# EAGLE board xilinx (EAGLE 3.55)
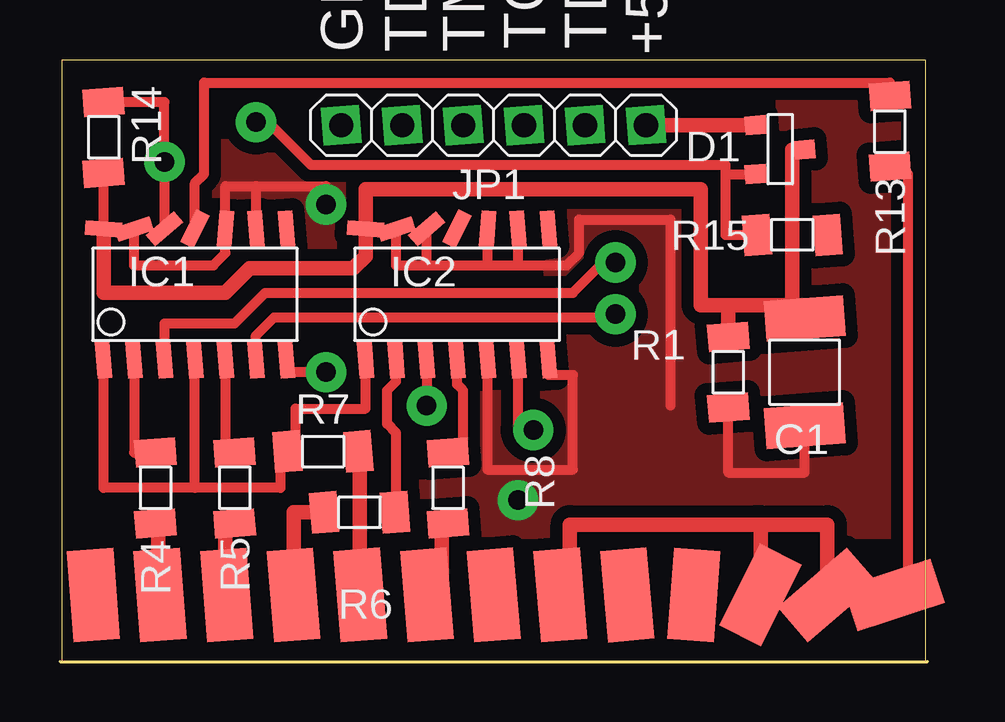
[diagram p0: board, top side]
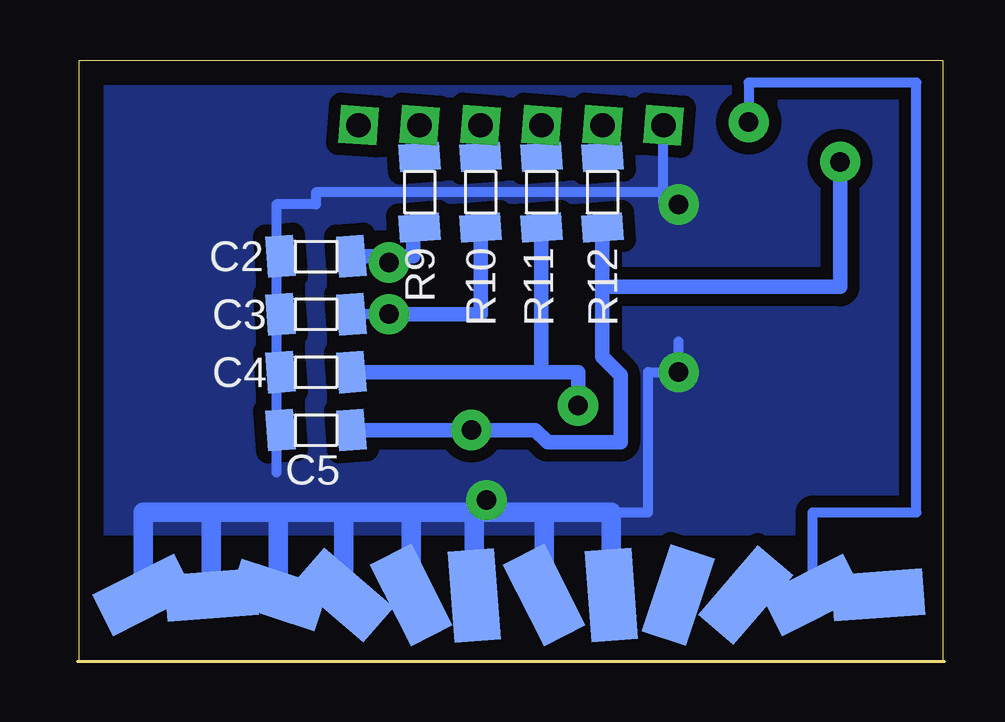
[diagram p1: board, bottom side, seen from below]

Size 36.14 x 25.07 mm. Coordinates in mm from the lower left corner, seen from the top.
Outline: 36.07,0.01 36.07,25.07 0.07,25.07 0.07,0.01 36.07,0.01
Copper layers used: Top, Bottom
tRestrict: area 13.8,16.6 to 19.7,18.7; area 10.4,21.3 to 12.9,23.1; area 2.6,16.9 to 8.5,18.7; area 6,11 to 11.8,14

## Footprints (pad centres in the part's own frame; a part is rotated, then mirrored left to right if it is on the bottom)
T-1812 = smd 1.702 x 3.302 rotated 4.4:  2.235,0 | smd 1.702 x 3.302 rotated 4.3:  -2.235,0
T-1206 = smd 1.143 x 1.702 rotated 4.4:  1.473,0 | smd 1.143 x 1.702 rotated 4.3:  -1.473,0
T-23 = smd 0.787 x 0.889 rotated 4.4:  1.016,1.016 | smd 0.787 x 0.889 rotated 4.3:  -1.016,1.016 | smd 0.787 x 0.889 rotated 4.5:  0,-1.016
-14 = smd 0.61 x 1.524 rotated 4.3:  -3.81,-2.794;  1.27,2.667 | smd 0.61 x 1.524 rotated 94.3:  -3.81,2.667 | smd 0.61 x 1.524 rotated 4.4:  -2.54,-2.794 | smd 0.61 x 1.524 rotated 4.5:  -1.27,-2.794 | smd 0.61 x 1.524 rotated 71.8:  -2.54,2.667 | smd 0.61 x 1.524 rotated 49.3:  -1.27,2.667 | smd 0.61 x 1.524 rotated 4.6:  0,-2.794 | smd 0.61 x 1.524 rotated 26.8:  0,2.667 | smd 0.61 x 1.524 rotated 4.7:  1.27,-2.794;  2.54,-2.794 | smd 0.61 x 1.524 rotated 5:  2.54,2.667 | smd 0.61 x 1.524 rotated 4.8:  3.81,-2.794 | smd 0.61 x 1.524 rotated 4.9:  3.81,2.667
06 = drill 1.016 pad 1.575 square:  -6.35,0;  -3.81,0;  -1.27,0;  1.27,0;  3.81,0;  6.35,0
D-1206 = smd 1.143 x 1.702 rotated 4.4:  1.473,0 | smd 1.143 x 1.702 rotated 4.3:  -1.473,0
G-DB25 = smd 3.81 x 1.93 rotated 4.9:  2.78,-2.78 | smd 3.81 x 1.93 rotated 4.8:  2.78,0 | smd 3.81 x 1.93 rotated 4.7:  2.78,2.78;  2.78,5.56 | smd 3.81 x 1.93 rotated 4.6:  2.78,8.34 | smd 3.81 x 1.93 rotated 4.5:  2.78,11.12 | smd 3.81 x 1.93 rotated 4.4:  2.78,13.9 | smd 3.81 x 1.93 rotated 4.3:  2.78,16.68;  2.78,-8.34 | smd 3.81 x 1.93 rotated 5:  2.78,-5.56 | smd 3.81 x 1.93 rotated 26.8:  2.78,-11.12 | smd 3.81 x 1.93 rotated 49.3:  2.78,-13.9 | smd 3.81 x 1.93 rotated 71.8:  2.78,-16.68 | smd 3.81 x 1.93 rotated 94.3 bottom:  2.78,15.292 | smd 3.81 x 1.93 rotated 116.8 bottom:  2.78,12.56 | smd 3.81 x 1.93 rotated 139.3 bottom:  2.78,9.777 | smd 3.81 x 1.93 rotated 161.8 bottom:  2.78,6.969 | smd 3.81 x 1.93 rotated 184.3 bottom:  2.78,4.187 | smd 3.81 x 1.93 rotated 206.8 bottom:  2.78,1.379 | smd 3.81 x 1.93 rotated 4.4 bottom:  2.755,-1.531 | smd 3.81 x 1.93 rotated 26.9 bottom:  2.78,-4.161 | smd 3.81 x 1.93 rotated 49.4 bottom:  2.78,-6.969 | smd 3.81 x 1.93 rotated 71.9 bottom:  2.78,-9.701 | smd 3.81 x 1.93 rotated 94.4 bottom:  2.78,-12.484 | smd 3.81 x 1.93 rotated 116.9 bottom:  2.78,-15.317

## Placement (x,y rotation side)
C1  330nF  [T-1812]  31.02,12.06 90 top
C2  82p  [T-1206]  26.2,16.89 0 bottom
C3  82p  [T-1206]  26.2,14.48 0 bottom
C4  82p  [T-1206]  26.2,12.06 0 bottom
C5  82p  [T-1206]  26.2,9.65 0 bottom
D1  BAR-43-S  [T-23]  30.01,21.34 90 top
IC1  74125  [-14]  5.62,15.37 0 top
IC2  74125  [-14]  16.55,15.37 0 top
JP1  PINHD-1X6  [06]  18.07,22.35 180 top
R1  22k  [D-1206]  27.85,12.06 90 top
R4  330  [D-1206]  3.97,7.24 270 top
R5  330  [D-1206]  7.28,7.24 270 top
R6  330  [D-1206]  12.48,6.22 180 top
R7  330  [D-1206]  10.96,8.76 0 top
R8  330  [D-1206]  16.16,7.24 270 top
R9  100  [D-1206]  21.88,19.56 270 bottom
R10  100  [D-1206]  19.34,19.56 270 bottom
R11  100  [D-1206]  16.8,19.56 270 bottom
R12  100  [D-1206]  14.26,19.56 270 bottom
R13  47  [D-1206]  34.58,22.1 90 top
R14  6k8  [D-1206]  1.81,21.84 270 top
R15  1k  [D-1206]  30.52,17.78 180 top
X1  LP25DBM  [G-DB25]  18.07,0 90 top

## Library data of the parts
C1-C5 = C_KERAM
D1 = DIODEN
IC1 IC2 = 74499SMD
JP1 = PINHD-Q
R1 R4-R15 = R
X1 = Z_CONNEC

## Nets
+VERSORG: D1. JP1.
ACK: X1.
AUTOFD: X1.
CLK: IC1. R5.
CTRL: IC1. IC2. R7.
D0: R4. X1.
D1: R5. X1.
D2: R6. X1.
D3: R7. X1.
D4: R8. X1.
D5: X1.
D6: X1.
D7: X1.
DIN: IC1. R4.
ERR: D1. R15. X1.
GND: C1. C2. C3. C4. C5. IC1. IC2. JP1. R1. R15. X1.
INIT: X1.
N$1: C2. IC1. R9.
N$2: C3. IC1. R10.
N$3: C4. IC2. R11.
N$4: C5. IC1. IC2. R12. R14.
N$6: IC1. R13.
PROG: IC2. R8.
SELECT: R13. X1.
SELECTIN: X1.
STROBE: X1.
TCK: JP1. R10.
TDI: JP1. R9.
TDO: JP1. R12.
TMS: JP1. R11.
TMS-IN: IC2. R6.
VCC: C1. D1. IC1. IC2. R1. R14.

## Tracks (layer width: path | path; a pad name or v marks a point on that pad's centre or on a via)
+VERSORG
  Top 0.61: 24.42,22.35 28.99,22.35
CLK
  Top 0.406: R5. 6.89,8.71 6.89,12.57
CTRL
  Top 0.406: 1.81,12.57 1.81,7.24 5.62,7.24 | 5.62,7.24 5.62,12.57 | 5.62,7.24 9.18,7.24 9.18,8.76 R7. 9.81,8.76 9.81,10.54 12.74,10.54 12.74,12.57
D0
  Top 0.61: 4.17,2.78 4.1,2.78 4.1,5.77 3.97,5.77
D1
  Top 0.61: 6.95,2.78 6.89,2.78 6.89,5.77 7.28,5.77
D2
  Top 0.61: 9.73,2.78 9.73,6.22 11.01,6.22
D3
  Top 0.406: 11.85,2.78 12.48,2.78 12.51,2.78 | 12.43,8.76 12.48,8.76
  Top 0.61: 12.48,8.76 12.48,2.78
D4
  Top 0.406: 15.29,2.78 15.91,2.78 | 15.91,5.77 16.16,5.77
  Top 0.61: 15.91,2.78 15.91,5.77
D6
  Top 0.406: 28.99,5.71 29.12,5.71 29.19,5.71
  Top 0.61: 20.85,2.78 21.25,2.78 21.25,5.71 28.99,5.71 | 31.97,2.78 31.97,5.71 29.12,5.71 | 29.19,5.71 29.19,2.78
DIN
  Top 0.406: R4. 3.08,8.71 3.08,12.57
ERR  (via drill 0.81 pad 1.68)
  Top 0.406: v8.16,22.48 8.67,22.48 10.45,20.7 27.72,20.7 27.72,20.32 | 27.72,20.32 28.99,20.32 | 29.04,17.78 27.72,17.78 27.72,20.32
  Bottom 0.406: 5.51,2.78 5.51,6.22 1.18,6.22 1.18,24.13 8.16,24.13 v8.16,22.48
GND  (via drill 0.81 pad 1.68)
  Top 0.406: 9.43,12.57 9.43,12.06 v11.09,12.06 | C1. 31.02,7.87 27.85,7.87 R1. | 17.82,12.57 17.82,8 21.37,8 21.37,11.94 20.36,11.94 20.36,12.57 | 19.09,16.51 19.09,18.03 | 15.28,16.51 17.82,16.51 | 15.28,16.51 15.28,18.03 | 15.28,16.51 14.01,16.51 14.01,18.03 | 17.82,16.51 17.82,18.03 | 17.82,16.51 19.09,16.51 | 19.09,16.51 21.12,16.51 21.63,17.02 21.63,18.41 25.44,18.41 25.44,10.67 | 8.16,19.81 11.09,19.81 v11.09,19.05 | 8.16,19.81 8.16,18.03 | 8.16,19.81 6.89,19.81 6.89,18.03 6.89,17.02 6.39,16.51 3.08,16.51 3.08,18.03
  Bottom 0.406: 11.09,13.34 v11.09,12.06 12.36,12.06 12.36,6.22 15,6.22 | 27.85,9.65 27.85,7.87 | 27.85,9.65 C5. | 27.85,12.06 27.85,9.65 | 27.85,12.06 C4. | 27.85,14.48 27.85,12.06 | 27.85,16.89 C2. | 27.85,14.48 C3. | 27.85,16.89 27.85,14.48 | 27.85,16.89 27.85,19.05 26.2,19.05 26.2,19.56 11.72,19.56 | 11.72,19.56 JP1. | 11.72,19.56 11.72,19.05 v11.09,19.05
  Bottom 0.813: 30.55,6.22 33.39,6.22 X1. | 27.77,6.22 27.77,2.78 | 30.55,6.22 30.55,2.78 | 27.77,6.22 30.55,6.22 | 25.04,6.22 25.04,2.78 | 23.68,6.22 22.23,6.22 22.23,2.78 | 19.6,6.22 19.6,2.75 | 18.95,6.22 16.69,6.22 16.69,2.78 | 13.88,2.78 13.88,6.22 15,6.22 18.95,6.22 | 25.04,6.22 27.77,6.22 | 23.68,6.22 25.04,6.22 | 19.6,6.22 23.68,6.22 | 18.95,6.22 19.6,6.22
  other vias: 19.09,6.73
  pour Top (isolate 0.508): 0.29,5.33 35.72,5.33 35.72,24.89 0.29,24.89
  pour Bottom (isolate 0.508): 0.29,5.46 35.72,5.46 35.72,24.77 0.29,24.77
N$1  (via drill 0.81 pad 1.68)
  Top 0.406: 4.35,12.57 4.35,14.1 7.28,14.1 8.54,15.37 21.37,15.37 22.64,16.64 v23.15,16.64
  Bottom 0.406: 22.13,18.09 21.88,18.09 | v23.15,16.64 23.15,16.89
  Bottom 0.61: 22.13,18.09 22.13,16.89 23.15,16.89 24.73,16.89
N$2  (via drill 0.81 pad 1.68)
  Top 0.406: v23.15,14.48 23.15,14.35 8.93,14.35 8.16,13.59 8.16,12.57
  Bottom 0.406: v23.15,14.48 24.73,14.48
  Bottom 0.61: 19.34,18.09 19.34,14.48 v23.15,14.48
N$3  (via drill 0.81 pad 1.68)
  Top 0.406: 15.28,12.57 v15.28,10.67
  Bottom 0.61: 16.8,12.06 16.8,18.09 | v15.28,10.67 15.28,12.06 16.8,12.06 | 16.8,12.06 24.73,12.06
N$4  (via drill 0.81 pad 1.68)
  Top 0.406: v19.72,9.65 19.09,9.65 19.09,12.57 | R14. 4.35,23.32 v4.35,20.83 4.35,18.03
  Bottom 0.61: 24.73,9.65 v19.72,9.65 17.05,9.65 16.55,9.14 13.5,9.14 13.5,11.94 14.26,12.7 14.26,18.09 14.26,15.62 4.35,15.62 v4.35,20.83
N$6
  Top 0.406: 34.58,23.57 34.58,24.13 6.01,24.13 6.01,20.32 5.62,19.94 5.62,18.03
PROG
  Top 0.406: R8. 16.8,8.71 16.8,11.3 16.55,11.56 16.55,12.57
SELECT
  Top 0.406: 34.75,2.78 35.34,2.78 35.34,20.32 34.58,20.32 R13.
TCK
  Bottom 0.61: 19.34,22.35 R10.
TDI
  Bottom 0.61: 21.88,22.35 R9.
TDO
  Bottom 0.61: 14.26,22.35 R12.
TMS
  Bottom 0.61: 16.8,22.35 R11.
TMS-IN
  Top 0.406: R6. 14.01,6.22 14.01,9.53 13.62,9.91 13.62,11.3 14.01,11.68 14.01,12.57
VCC
  Top 0.406: 31.02,14.86 31.02,14.3 | 1.81,18.03 1.81,20.37
  Top 0.61: 27.85,14.86 27.85,13.54 | 30.52,14.86 30.52,21.34 D1. | 27.85,14.86 30.52,14.86 | 30.52,14.86 31.02,14.86 | 27.85,14.86 26.71,14.86 26.71,19.68 12.74,19.68 12.74,18.03 12.74,16.89 12.23,16.38 7.91,16.38 6.89,15.37 1.81,15.37 1.81,18.03

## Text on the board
tPlace: TCK | TDI | GND | TDO | TMS | +5Volt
